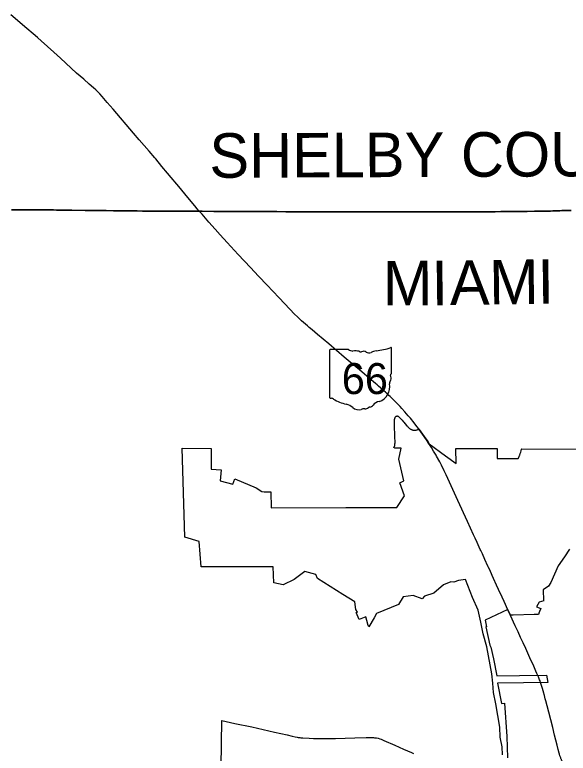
# Model space of a CAD drawing. Extents: x 0 to 34, y 0 to 22.
# Drawn here: x 4.8597 to 5.0595, y 17.5508 to 17.8172 of the extents above; entities that cross this region are included whole.
import ezdxf

# ---------------------------------------------------------------- set-up
doc = ezdxf.new("R2010")
doc.units = 0
for name, color, linetype in [('GM_X_Corporation', 7, 'Continuous'), ('GM_X_County', 7, 'Continuous'), ('GM_X_County_Text', 7, 'Continuous'), ('GM_X_State_Location', 7, 'Continuous'), ('GM_X_State_Route', 7, 'Continuous'), ('GM_X_State_Shield', 7, 'Continuous')]:
    doc.layers.add(name, color=color, linetype=linetype)

msp = doc.modelspace()

# ---------------------------------------------------------------- linework, layer by layer
at = {"layer": 'GM_X_Corporation'}
for points in [[(5.035828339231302, 17.550228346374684), (5.035652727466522, 17.55305342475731), (5.034947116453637, 17.556590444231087), (5.0348015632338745, 17.560101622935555), (5.033406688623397, 17.568526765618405), (5.032585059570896, 17.572625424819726), (5.032356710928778, 17.576022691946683), (5.0319722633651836, 17.579377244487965), (5.030132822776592, 17.589148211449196), (5.028835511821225, 17.593800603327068), (5.0279384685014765, 17.598027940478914), (5.026952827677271, 17.602422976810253), (5.024957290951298, 17.60698993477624), (5.022432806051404, 17.6134569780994), (5.019858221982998, 17.613112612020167), (5.018258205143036, 17.61252987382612), (5.017105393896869, 17.612554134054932), (5.01452764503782, 17.611573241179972), (5.01094738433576, 17.608541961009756), (5.007608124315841, 17.60746983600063), (5.00683923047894, 17.606484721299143), (5.0035722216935, 17.60764913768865), (4.999884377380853, 17.607177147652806), (4.998279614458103, 17.604415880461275), (4.9902969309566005, 17.601117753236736), (4.98940535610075, 17.599584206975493), (4.987563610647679, 17.59641631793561), (4.987162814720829, 17.597143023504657), (4.987122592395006, 17.59729673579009), (4.9864260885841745, 17.59995861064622), (4.9840872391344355, 17.5990130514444), (4.9836511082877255, 17.599881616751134), (4.983007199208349, 17.601569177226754), (4.983485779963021, 17.601655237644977), (4.9828942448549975, 17.602624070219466), (4.982487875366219, 17.605373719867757), (4.978181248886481, 17.60804845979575), (4.969014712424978, 17.613741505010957), (4.968347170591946, 17.615302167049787), (4.964399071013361, 17.61634845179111), (4.960569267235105, 17.613498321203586), (4.956656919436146, 17.611549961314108), (4.953183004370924, 17.612215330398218), (4.953002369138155, 17.617996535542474), (4.926995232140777, 17.617950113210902), (4.9263265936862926, 17.627198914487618), (4.92110926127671, 17.62870045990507), (4.920146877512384, 17.660789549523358), (4.930614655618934, 17.660738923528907), (4.930563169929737, 17.653282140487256), (4.9341978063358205, 17.652962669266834), (4.933898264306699, 17.648991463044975), (4.938416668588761, 17.647801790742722), (4.939122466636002, 17.649813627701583), (4.946810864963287, 17.646484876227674), (4.94884574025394, 17.645130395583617), (4.94974835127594, 17.645104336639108), (4.952136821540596, 17.64503538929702), (4.952321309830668, 17.63927231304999), (4.979243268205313, 17.63937684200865), (4.997663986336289, 17.639430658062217), (5.000415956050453, 17.64359362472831), (4.998723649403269, 17.648319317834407), (5.00018443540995, 17.64909213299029), (4.998404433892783, 17.656844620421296), (4.999165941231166, 17.660823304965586), (4.996880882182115, 17.660840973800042), (4.996556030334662, 17.66110149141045), (4.996618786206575, 17.661171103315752), (4.996681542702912, 17.661254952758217), (4.996750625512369, 17.661378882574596), (4.996822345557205, 17.661520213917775), (4.996877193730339, 17.661687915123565), (4.996918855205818, 17.661840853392), (4.996943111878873, 17.66200697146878), (4.996974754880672, 17.662398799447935), (4.9969884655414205, 17.66269886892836), (4.996989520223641, 17.663018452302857), (4.996963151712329, 17.664919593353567), (4.996903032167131, 17.666342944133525), (4.996826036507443, 17.667815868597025), (4.996788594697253, 17.668709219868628), (4.996779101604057, 17.66931990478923), (4.996772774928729, 17.670183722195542), (4.996800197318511, 17.670819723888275), (4.996828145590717, 17.67101484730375), (4.996856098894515, 17.671259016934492), (4.996890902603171, 17.67146152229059), (4.9969325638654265, 17.671628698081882), (4.996988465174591, 17.671803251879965), (4.9970306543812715, 17.671900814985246), (4.997086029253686, 17.671998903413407), (4.997144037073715, 17.672079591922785), (4.997204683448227, 17.672159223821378), (4.997265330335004, 17.67223147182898), (4.997337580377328, 17.672298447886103), (4.997428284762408, 17.67235434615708), (4.997525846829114, 17.672396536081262), (4.997616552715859, 17.672417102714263), (4.997700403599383, 17.672431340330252), (4.997783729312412, 17.672431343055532), (4.997860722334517, 17.672424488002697), (4.997951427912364, 17.672410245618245), (4.998048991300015, 17.67238229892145), (4.998132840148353, 17.672340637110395), (4.998228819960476, 17.672274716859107), (4.998349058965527, 17.672180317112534), (4.99850938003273, 17.672040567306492), (4.998649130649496, 17.671887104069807), (4.9988442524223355, 17.671677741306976), (4.999151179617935, 17.67134286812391), (4.999548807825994, 17.67088248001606), (4.9998836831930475, 17.67049170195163), (5.000142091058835, 17.670191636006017), (5.000700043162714, 17.669549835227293), (5.001167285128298, 17.6690198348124), (5.001439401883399, 17.66871291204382), (5.001613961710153, 17.66852411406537), (5.001774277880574, 17.668363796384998), (5.001927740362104, 17.668217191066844), (5.002088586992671, 17.668077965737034), (5.0022420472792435, 17.667952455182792), (5.00240236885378, 17.667833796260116), (5.00254897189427, 17.667736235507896), (5.002709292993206, 17.667638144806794), (5.002883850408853, 17.667547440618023), (5.003072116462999, 17.667470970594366), (5.0032466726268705, 17.66740821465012), (5.003385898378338, 17.667366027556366), (5.0035467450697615, 17.667331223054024), (5.003713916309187, 17.667303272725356), (5.003860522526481, 17.667282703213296), (5.004013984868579, 17.667275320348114), (5.004139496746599, 17.667282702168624), (5.004327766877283, 17.667303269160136), (5.004495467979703, 17.667331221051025), (5.004669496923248, 17.667373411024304), (5.004822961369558, 17.667428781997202), (5.004976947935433, 17.667492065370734), (5.005213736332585, 17.66761757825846), (5.005557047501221, 17.667798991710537), (5.005724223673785, 17.667580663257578), (5.007501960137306, 17.665092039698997), (5.008804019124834, 17.66317085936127), (5.009294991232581, 17.662394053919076), (5.015272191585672, 17.658038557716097), (5.019028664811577, 17.65534842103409), (5.018946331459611, 17.66071406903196), (5.0338572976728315, 17.66067317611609), (5.033849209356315, 17.657056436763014), (5.041423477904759, 17.657061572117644), (5.041476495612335, 17.657161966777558), (5.041526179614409, 17.65726358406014), (5.04168199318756, 17.657577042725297), (5.041804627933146, 17.6578400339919), (5.041932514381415, 17.658129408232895), (5.041963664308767, 17.658201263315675), (5.041992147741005, 17.65826695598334), (5.042092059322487, 17.658500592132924), (5.042180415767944, 17.65872048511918), (5.042231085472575, 17.65887787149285), (5.042312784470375, 17.659146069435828), (5.0423866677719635, 17.659380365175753), (5.042503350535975, 17.6598115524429), (5.042566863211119, 17.660055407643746), (5.042643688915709, 17.66033323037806), (5.042687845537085, 17.66048919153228), (5.042715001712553, 17.660584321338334), (5.084355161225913, 17.66037640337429)], [(5.060034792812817, 17.624336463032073), (5.058140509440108, 17.621624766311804), (5.055891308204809, 17.618428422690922), (5.053240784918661, 17.612400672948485), (5.052455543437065, 17.611030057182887), (5.050495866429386, 17.60972536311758), (5.0506551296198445, 17.605868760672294), (5.050661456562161, 17.60571318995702), (5.049080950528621, 17.605311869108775), (5.04809741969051, 17.603573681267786), (5.049676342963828, 17.60295297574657), (5.0491452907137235, 17.601874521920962), (5.048868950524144, 17.60131288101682), (5.048863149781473, 17.601041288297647), (5.048825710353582, 17.60083456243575), (5.0471703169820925, 17.600781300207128), (5.0396754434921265, 17.60054029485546), (5.03865921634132, 17.600535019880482), (5.037712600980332, 17.602590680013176), (5.029486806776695, 17.598769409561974), (5.029997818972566, 17.596396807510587), (5.029766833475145, 17.596389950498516), (5.031276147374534, 17.589689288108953), (5.031611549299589, 17.58896627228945), (5.032599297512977, 17.584782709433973), (5.033698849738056, 17.578686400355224), (5.0419230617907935, 17.578742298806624), (5.0517161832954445, 17.578892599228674), (5.052186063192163, 17.57628689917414), (5.043384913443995, 17.576194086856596), (5.034024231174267, 17.576053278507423), (5.035472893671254, 17.56868813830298), (5.036464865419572, 17.56876460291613), (5.037327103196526, 17.556761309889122), (5.037553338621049, 17.54913670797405)], [(4.934070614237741, 17.53738337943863), (4.934486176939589, 17.56258286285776), (4.939213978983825, 17.56153763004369), (4.945246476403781, 17.560233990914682), (4.953484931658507, 17.55839244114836), (4.9580075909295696, 17.55734246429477), (4.959858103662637, 17.55691793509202), (4.96099140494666, 17.55667851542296), (4.9616100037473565, 17.55654772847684), (4.961984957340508, 17.55648286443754), (4.962330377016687, 17.556420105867), (4.9626599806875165, 17.556381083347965), (4.962960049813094, 17.556346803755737), (4.963745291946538, 17.556277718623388), (4.965955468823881, 17.55615959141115), (4.967588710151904, 17.556112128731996), (4.9696448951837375, 17.556073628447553), (4.971964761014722, 17.556077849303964), (4.975550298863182, 17.556127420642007), (4.9825120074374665, 17.556291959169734), (4.986519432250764, 17.556381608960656), (4.988315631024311, 17.556413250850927), (4.98916468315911, 17.55639637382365), (4.9896277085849, 17.556365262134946), (4.989981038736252, 17.556318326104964), (4.990324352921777, 17.55625135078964), (4.990844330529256, 17.556137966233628), (4.99145923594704, 17.5559676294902), (4.991960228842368, 17.555790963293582), (4.99294112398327, 17.55539227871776), (4.996949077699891, 17.55362614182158), (4.999996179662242, 17.55226818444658), (5.0028898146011, 17.55100251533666), (5.003692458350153, 17.55062017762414)]]:
    msp.add_lwpolyline(points, dxfattribs=at)
at = {"layer": 'GM_X_County'}
for points in [[(5.0605378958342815, 17.74658801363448), (5.058746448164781, 17.746552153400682), (5.057217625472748, 17.746518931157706), (5.056533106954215, 17.74650047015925), (5.055849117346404, 17.746477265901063), (5.054586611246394, 17.746429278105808), (5.053954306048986, 17.7464055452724), (5.053162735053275, 17.74638550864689), (5.0523184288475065, 17.74638023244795), (5.0508950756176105, 17.746369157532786), (5.047310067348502, 17.746293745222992), (5.044673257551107, 17.746265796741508), (5.04108824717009, 17.74621780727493), (5.039296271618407, 17.746196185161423), (5.037241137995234, 17.74617034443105), (5.035237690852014, 17.746165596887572), (5.033182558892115, 17.746147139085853), (5.031020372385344, 17.746118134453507), (5.029227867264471, 17.746100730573), (5.027381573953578, 17.74610178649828), (5.025378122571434, 17.74610231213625), (5.022636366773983, 17.74608438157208), (5.01968419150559, 17.746089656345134), (5.01836578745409, 17.74608227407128), (5.014357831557, 17.746069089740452), (5.009084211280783, 17.74606803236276), (5.00676381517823, 17.746070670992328), (5.00064641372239, 17.746102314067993), (4.9986429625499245, 17.746101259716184), (4.996269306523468, 17.746110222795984), (4.996044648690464, 17.746112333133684), (4.994002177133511, 17.746134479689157), (4.990100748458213, 17.746127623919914), (4.9867788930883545, 17.746135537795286), (4.983457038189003, 17.746150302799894), (4.980452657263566, 17.74614450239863), (4.976603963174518, 17.746102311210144), (4.975338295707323, 17.7460917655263), (4.97470546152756, 17.74608965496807), (4.9735979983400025, 17.746085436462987), (4.971224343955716, 17.746103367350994), (4.968851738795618, 17.746114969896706), (4.966953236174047, 17.746118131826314), (4.963789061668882, 17.74613869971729), (4.9603089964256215, 17.74614924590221), (4.957566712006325, 17.746155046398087), (4.954350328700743, 17.746164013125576), (4.9534770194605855, 17.74616137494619), (4.952452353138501, 17.746158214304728), (4.950448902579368, 17.74617034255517), (4.94691662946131, 17.746200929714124), (4.943910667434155, 17.74620040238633), (4.9411683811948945, 17.746209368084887), (4.938953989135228, 17.74621569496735), (4.936158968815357, 17.74622729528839), (4.934630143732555, 17.746239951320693), (4.93320573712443, 17.7462404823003), (4.93151870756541, 17.746258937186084), (4.927360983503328, 17.746304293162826), (4.9263785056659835, 17.74631483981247), (4.925876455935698, 17.746320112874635), (4.92545562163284, 17.746325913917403), (4.922135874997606, 17.746304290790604), (4.920500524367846, 17.746311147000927), (4.918866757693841, 17.746324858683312), (4.916493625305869, 17.746325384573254), (4.914384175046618, 17.746336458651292), (4.911061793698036, 17.746338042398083), (4.909426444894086, 17.746355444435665), (4.9081618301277, 17.74638075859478), (4.905842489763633, 17.746376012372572), (4.903943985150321, 17.746396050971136), (4.902625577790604, 17.746409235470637), (4.90125496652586, 17.74643138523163), (4.899884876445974, 17.746437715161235), (4.89851373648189, 17.746440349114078), (4.895401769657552, 17.746483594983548), (4.8926605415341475, 17.746529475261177), (4.890868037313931, 17.746543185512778), (4.890393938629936, 17.746545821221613), (4.889814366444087, 17.746545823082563), (4.887469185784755, 17.746582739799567), (4.885138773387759, 17.746619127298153), (4.8802849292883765, 17.74669506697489), (4.87918168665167, 17.74671932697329), (4.8774793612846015, 17.746735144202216), (4.875704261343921, 17.746751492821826), (4.874808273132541, 17.7467509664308), (4.87370081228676, 17.74675993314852), (4.8723307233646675, 17.746773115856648), (4.869906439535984, 17.74679632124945), (4.868852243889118, 17.746810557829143), (4.867992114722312, 17.746822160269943), (4.86663837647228, 17.746841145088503), (4.865109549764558, 17.746839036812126), (4.863845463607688, 17.746838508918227), (4.862266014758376, 17.74682532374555), (4.86131623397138, 17.746825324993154), (4.858469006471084, 17.746863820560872)], [(4.858469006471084, 17.746863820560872), (4.86131623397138, 17.746825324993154), (4.862266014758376, 17.74682532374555), (4.863845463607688, 17.746838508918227), (4.865109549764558, 17.746839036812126), (4.86663837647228, 17.746841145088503), (4.867992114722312, 17.746822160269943), (4.868852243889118, 17.746810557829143), (4.869906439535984, 17.74679632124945), (4.8723307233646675, 17.746773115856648), (4.87370081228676, 17.74675993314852), (4.874808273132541, 17.7467509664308), (4.875704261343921, 17.746751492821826), (4.8774793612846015, 17.746735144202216), (4.87918168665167, 17.74671932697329), (4.8802849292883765, 17.74669506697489), (4.885138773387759, 17.746619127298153), (4.887469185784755, 17.746582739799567), (4.889814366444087, 17.746545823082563), (4.890393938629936, 17.746545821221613), (4.890868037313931, 17.746543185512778), (4.8926605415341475, 17.746529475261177), (4.895401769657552, 17.746483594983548), (4.89851373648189, 17.746440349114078), (4.899884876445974, 17.746437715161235), (4.90125496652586, 17.74643138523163), (4.902625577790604, 17.746409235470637), (4.903943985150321, 17.746396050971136), (4.905842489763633, 17.746376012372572), (4.9081618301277, 17.74638075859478), (4.909426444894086, 17.746355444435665), (4.911061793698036, 17.746338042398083), (4.914384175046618, 17.746336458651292), (4.916493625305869, 17.746325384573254), (4.918866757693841, 17.746324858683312), (4.920500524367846, 17.746311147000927), (4.922135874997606, 17.746304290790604), (4.92545562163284, 17.746325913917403), (4.925876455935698, 17.746320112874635), (4.9263785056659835, 17.74631483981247), (4.927360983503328, 17.746304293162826), (4.93151870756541, 17.746258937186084), (4.93320573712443, 17.7462404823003), (4.934630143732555, 17.746239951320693), (4.936158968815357, 17.74622729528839), (4.938953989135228, 17.74621569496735), (4.9411683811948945, 17.746209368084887), (4.943910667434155, 17.74620040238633), (4.94691662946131, 17.746200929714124), (4.950448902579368, 17.74617034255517), (4.952452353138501, 17.746158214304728), (4.9534770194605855, 17.74616137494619), (4.954350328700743, 17.746164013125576), (4.957566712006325, 17.746155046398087), (4.9603089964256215, 17.74614924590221), (4.963789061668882, 17.74613869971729), (4.966953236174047, 17.746118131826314), (4.968851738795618, 17.746114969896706), (4.971224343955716, 17.746103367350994), (4.9735979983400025, 17.746085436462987), (4.97470546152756, 17.74608965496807), (4.975338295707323, 17.7460917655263), (4.976603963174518, 17.746102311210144), (4.980452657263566, 17.74614450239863), (4.983457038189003, 17.746150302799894), (4.9867788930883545, 17.746135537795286), (4.990100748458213, 17.746127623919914), (4.994002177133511, 17.746134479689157), (4.996044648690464, 17.746112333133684), (4.996269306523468, 17.746110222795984), (4.9986429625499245, 17.746101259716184), (5.00064641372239, 17.746102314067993), (5.00676381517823, 17.746070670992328), (5.009084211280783, 17.74606803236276), (5.014357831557, 17.746069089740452), (5.01836578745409, 17.74608227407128), (5.01968419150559, 17.746089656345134), (5.022636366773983, 17.74608438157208), (5.025378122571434, 17.74610231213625), (5.027381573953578, 17.74610178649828), (5.029227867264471, 17.746100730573), (5.031020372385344, 17.746118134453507), (5.033182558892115, 17.746147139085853), (5.035237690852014, 17.746165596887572), (5.037241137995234, 17.74617034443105), (5.039296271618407, 17.746196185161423), (5.04108824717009, 17.74621780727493), (5.044673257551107, 17.746265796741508), (5.047310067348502, 17.746293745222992), (5.0508950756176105, 17.746369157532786), (5.0523184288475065, 17.74638023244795), (5.053162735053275, 17.74638550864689), (5.053954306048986, 17.7464055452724), (5.054586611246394, 17.746429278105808), (5.055849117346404, 17.746477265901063), (5.056533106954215, 17.74650047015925), (5.057217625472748, 17.746518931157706), (5.058746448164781, 17.746552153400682), (5.0605378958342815, 17.74658801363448)]]:
    msp.add_lwpolyline(points, dxfattribs=at)
at = {"layer": 'GM_X_State_Route'}
msp.add_line((5.038678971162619, 17.60048939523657), (5.037732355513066, 17.60254505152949), dxfattribs=at)
for points in [[(4.86798394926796, 17.808922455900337), (4.867880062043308, 17.809014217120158), (4.866363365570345, 17.810322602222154), (4.864075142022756, 17.81227173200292), (4.858295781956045, 17.81719676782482)], [(4.92639828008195, 17.746269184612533), (4.926191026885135, 17.74651546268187), (4.925598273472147, 17.747220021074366), (4.924743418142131, 17.748226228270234), (4.9215924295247, 17.751984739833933), (4.919530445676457, 17.754453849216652), (4.914888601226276, 17.75999009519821), (4.912834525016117, 17.762466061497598), (4.91058690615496, 17.765190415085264), (4.910245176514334, 17.765591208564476), (4.908229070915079, 17.76796064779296), (4.904665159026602, 17.77212892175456), (4.902594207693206, 17.774521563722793), (4.895176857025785, 17.783165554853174), (4.893076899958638, 17.78560249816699), (4.891282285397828, 17.78767450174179), (4.890364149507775, 17.78868914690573), (4.889593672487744, 17.789480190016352), (4.888987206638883, 17.790063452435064), (4.888167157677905, 17.79080492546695), (4.886617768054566, 17.792155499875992), (4.884578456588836, 17.793909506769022), (4.882005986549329, 17.796176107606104), (4.88009007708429, 17.797912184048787), (4.876159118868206, 17.801505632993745), (4.87378230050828, 17.80367361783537), (4.869223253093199, 17.80782817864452), (4.86798394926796, 17.808922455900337)], [(4.9591556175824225, 17.710818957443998), (4.958975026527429, 17.71100342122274), (4.9551864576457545, 17.715029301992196), (4.952814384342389, 17.71752952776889), (4.950784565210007, 17.71968221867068), (4.947721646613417, 17.722919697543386), (4.944847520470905, 17.725968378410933), (4.940347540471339, 17.730726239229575), (4.936377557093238, 17.73497519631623), (4.933901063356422, 17.73777285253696), (4.932017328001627, 17.739886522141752), (4.929757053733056, 17.74241205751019), (4.927315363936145, 17.745216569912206), (4.92639828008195, 17.746269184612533)], [(4.996431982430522, 17.67827409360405), (4.996250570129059, 17.678457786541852), (4.995685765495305, 17.67900202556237), (4.995190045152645, 17.679476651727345), (4.994785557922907, 17.6798600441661), (4.994366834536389, 17.680250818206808), (4.9939692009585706, 17.680613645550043), (4.993515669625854, 17.68101813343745), (4.992999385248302, 17.68148590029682), (4.9923997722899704, 17.68201590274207), (4.991708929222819, 17.68262289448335), (4.991067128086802, 17.6831671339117), (4.990516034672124, 17.683641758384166), (4.989957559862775, 17.684115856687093), (4.98769042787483, 17.686041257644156), (4.98596701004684, 17.68749941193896), (4.984139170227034, 17.68904142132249), (4.98077671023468, 17.691887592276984), (4.97866251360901, 17.693708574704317), (4.973095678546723, 17.698431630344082), (4.969041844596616, 17.701864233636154), (4.96712330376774, 17.70348270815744), (4.966035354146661, 17.704404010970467), (4.965330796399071, 17.705003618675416), (4.964716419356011, 17.70552676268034), (4.963942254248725, 17.70619651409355), (4.963258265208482, 17.70680350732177), (4.962595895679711, 17.707424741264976), (4.9618702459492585, 17.708108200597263), (4.960600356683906, 17.709343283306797), (4.9591556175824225, 17.710818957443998)], [(5.005576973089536, 17.667753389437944), (5.004879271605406, 17.668666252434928), (5.003847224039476, 17.67000153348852), (5.002544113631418, 17.671593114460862), (5.001759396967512, 17.672517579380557), (5.000551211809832, 17.673970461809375), (4.999432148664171, 17.675171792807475), (4.9988182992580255, 17.67583468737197), (4.998322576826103, 17.676350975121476), (4.9978832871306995, 17.676811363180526), (4.997297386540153, 17.677404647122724), (4.996794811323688, 17.67790669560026), (4.996431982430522, 17.67827409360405)], [(5.009478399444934, 17.66209145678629), (5.009340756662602, 17.662307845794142), (5.008878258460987, 17.66303929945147), (5.008823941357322, 17.663125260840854), (5.007521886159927, 17.665046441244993), (5.0057441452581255, 17.66753506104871), (5.005576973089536, 17.667753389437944)], [(5.0266350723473, 17.626775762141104), (5.025893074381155, 17.62836207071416), (5.025328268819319, 17.629571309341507), (5.023113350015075, 17.634415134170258), (5.019663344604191, 17.641971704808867), (5.015432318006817, 17.6512010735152), (5.0147583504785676, 17.65263391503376), (5.013760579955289, 17.654648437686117), (5.013140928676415, 17.65583922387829), (5.01199391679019, 17.657919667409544), (5.011790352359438, 17.658270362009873), (5.010933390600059, 17.65974592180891), (5.010166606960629, 17.66100948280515), (5.009478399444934, 17.66209145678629)], [(5.037732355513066, 17.60254505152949), (5.036370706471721, 17.605525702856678), (5.035696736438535, 17.607004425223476), (5.034401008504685, 17.609794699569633), (5.033680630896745, 17.61144217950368), (5.032570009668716, 17.6138158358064), (5.032067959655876, 17.614888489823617), (5.031169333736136, 17.61687664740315), (5.030641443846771, 17.618007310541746), (5.030510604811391, 17.61830010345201), (5.029440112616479, 17.620695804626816), (5.028514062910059, 17.62269766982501), (5.027978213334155, 17.623858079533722), (5.027772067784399, 17.624304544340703), (5.0266350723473, 17.626775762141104)], [(5.048578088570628, 17.578811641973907), (5.048247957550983, 17.57958264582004), (5.047878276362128, 17.58040005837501), (5.047101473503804, 17.582132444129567), (5.045691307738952, 17.585197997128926), (5.044195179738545, 17.58851247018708), (5.043294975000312, 17.590535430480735), (5.0423272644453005, 17.592526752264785), (5.041448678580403, 17.594501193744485), (5.040419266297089, 17.596697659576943), (5.038678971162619, 17.60048939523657)], [(5.04957216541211, 17.576265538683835), (5.04934750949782, 17.576878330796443), (5.049196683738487, 17.577274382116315), (5.049068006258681, 17.57761347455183), (5.0489150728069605, 17.57799370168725), (5.048768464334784, 17.57835547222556), (5.048578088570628, 17.578811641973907)], [(5.050605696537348, 17.572941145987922), (5.050143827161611, 17.574475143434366), (5.04957216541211, 17.576265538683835)], [(5.055924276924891, 17.552116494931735), (5.055542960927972, 17.55367597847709), (5.054616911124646, 17.557325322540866), (5.053936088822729, 17.560048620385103), (5.053207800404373, 17.562853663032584), (5.052506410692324, 17.565583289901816), (5.051914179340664, 17.567823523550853), (5.0514717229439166, 17.569620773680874), (5.051251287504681, 17.57043976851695), (5.050967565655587, 17.57154089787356), (5.050654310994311, 17.572779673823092), (5.050605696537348, 17.572941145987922)], [(5.0581433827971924, 17.546554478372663), (5.0574615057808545, 17.547713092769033), (5.057356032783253, 17.547907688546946), (5.057253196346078, 17.54809754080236), (5.057136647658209, 17.548312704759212), (5.057060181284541, 17.548474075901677), (5.056975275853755, 17.548652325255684), (5.0568898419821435, 17.54883162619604), (5.056794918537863, 17.549069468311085), (5.0566963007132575, 17.549316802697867), (5.056618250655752, 17.54954989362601), (5.056547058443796, 17.549762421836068), (5.056496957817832, 17.549912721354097), (5.056406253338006, 17.550228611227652), (5.056340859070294, 17.550458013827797), (5.056265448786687, 17.550721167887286), (5.055924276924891, 17.552116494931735)]]:
    msp.add_lwpolyline(points, dxfattribs=at)
at = {"layer": 'GM_X_State_Shield'}
for p, q in [((4.97338862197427, 17.696126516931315), (4.97338862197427, 17.679142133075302)), ((4.980162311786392, 17.696418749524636), (4.97360888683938, 17.696418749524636)), ((4.995766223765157, 17.68795490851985), (4.995766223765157, 17.69683965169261)), ((4.9957640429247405, 17.6879570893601), (4.995766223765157, 17.68795490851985))]:
    msp.add_line(p, q, dxfattribs=at)
for centre, radius, start, end in [((4.987794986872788, 17.71957425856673), 0.02373123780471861, 275.8444694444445, 288.9064527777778), ((4.99551801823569, 17.69687649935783), 0.000249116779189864, 351.8620861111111, 97.738), ((4.973644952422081, 17.69616268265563), 0.0002592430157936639, 98.1301027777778, 188.13010277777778), ((4.981723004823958, 17.698390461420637), 0.0025145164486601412, 231.61950555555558, 271.11188333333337), ((4.982556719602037, 17.68688352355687), 0.009027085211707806, 80.48669166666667, 94.98826944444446), ((4.984606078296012, 17.69625073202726), 0.0007254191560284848, 219.79206111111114, 297.1023694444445), ((4.985671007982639, 17.694287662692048), 0.0015082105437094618, 54.466683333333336, 119.14113055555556), ((4.987617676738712, 17.696980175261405), 0.0018143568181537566, 233.85620555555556, 294.82819166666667), ((4.990821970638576, 17.691231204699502), 0.004774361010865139, 97.34618055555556, 120.7688527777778), ((4.9957086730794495, 17.68730265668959), 0.00038552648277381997, 107.94398333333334, 210.33696666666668), ((4.993255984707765, 17.686179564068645), 0.002314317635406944, 340.0329638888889, 23.649566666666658), ((4.995500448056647, 17.687920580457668), 0.0002666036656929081, 289.6038111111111, 7.734130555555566), ((4.9891243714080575, 17.68310649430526), 0.005935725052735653, 292.3088861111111, 8.985838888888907), ((4.996658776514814, 17.6842367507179), 0.001683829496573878, 136.80649722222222, 186.92959444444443), ((4.9736472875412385, 17.6791049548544), 0.00026154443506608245, 171.9583861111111, 258.30661388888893), ((4.973686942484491, 17.680842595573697), 0.0019959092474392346, 267.33899444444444, 280.6038555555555), ((4.974095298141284, 17.678162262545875), 0.000719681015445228, 29.748380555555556, 93.27174722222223), ((4.983181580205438, 17.693422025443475), 0.017137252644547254, 240.41292222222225, 257.1985), ((4.978072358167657, 17.6715118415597), 0.0053619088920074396, 47.184155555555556, 75.83597222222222), ((4.987508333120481, 17.677496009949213), 0.0019176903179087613, 282.8731916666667, 323.27711111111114), ((4.991627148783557, 17.674373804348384), 0.0032508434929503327, 94.40312222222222, 142.57675), ((4.983871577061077, 17.6780779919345), 0.003402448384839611, 230.70037222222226, 286.29183611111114), ((4.985837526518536, 17.672205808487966), 0.0027957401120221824, 85.69512222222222, 111.20994722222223), ((4.986086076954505, 17.676806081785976), 0.0018128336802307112, 268.7770194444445, 315.54927222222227), ((4.987725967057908, 17.675161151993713), 0.0005103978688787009, 65.75173055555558, 132.64842222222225)]:
    msp.add_arc(centre, radius, start, end, dxfattribs=at)

# ---------------------------------------------------------------- texts
at = {"layer": 'GM_X_County_Text'}
for s, height, rotation, p in [('SHELBY COUNTY', 0.016074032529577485, 0.22667000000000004, (4.929997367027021, 17.7583578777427)), ('I', 0.016074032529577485, 0.7940650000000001, (5.048530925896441, 17.712876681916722)), ('M', 0.016074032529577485, 0.148661, (4.992605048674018, 17.712318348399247)), ('I', 0.01607403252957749, 0.7176779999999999, (5.010248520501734, 17.71236480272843)), ('A', 0.016074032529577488, 0.7623519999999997, (5.016839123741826, 17.712447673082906)), ('M', 0.016074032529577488, 0.786735, (5.0310611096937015, 17.71263682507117))]:
    msp.add_text(s, height=height, rotation=rotation, dxfattribs=at).set_placement(p)
at = {"layer": 'GM_X_State_Location'}
for s, p in [('s', (4.984325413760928, 17.68650518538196)), ('r', (4.984324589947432, 17.68650518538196))]:
    msp.add_text(s, height=1.6074032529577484e-05, dxfattribs=at).set_placement(p)
msp.add_text('66', height=1.6074032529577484e-05, rotation=1.0000000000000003e-05, dxfattribs=at).set_placement((4.980277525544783, 17.685335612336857))
at = {"layer": 'GM_X_State_Shield'}
msp.add_text('66', height=0.011189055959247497, dxfattribs=at).set_placement((4.977761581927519, 17.680339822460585))

doc.saveas('drawing.dxf')
